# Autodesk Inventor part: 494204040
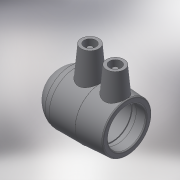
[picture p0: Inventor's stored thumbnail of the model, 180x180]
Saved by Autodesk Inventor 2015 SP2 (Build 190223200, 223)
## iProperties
Created: 2017-06
Part Number: 494204040
Material: Generic
Description: PLASSON END CAP MONOLITHIC 40
Document SubType Name: Modeling
Designer: Кирилл
Density: 1 g/cm^3
Appearance: Default
Author: Кирилл
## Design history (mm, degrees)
derived "494204.ipt"
feature "Solid1::494204.ipt"
tag "TaggingFeature1"
body "Solid1"
other parameters: "d1" = 1, "d2" = 48, "d4" = 55, "d5" = 7, "d7" = 1.65, "d8" = 24.5, "d10" = 1.1, "d11" = 14, "d12" = 168 deg, "d13" = 4.66667, "d15" = 51, "d16" = 15, "d17" = 35, "d18" = 1, "d20" = 5 deg, "d21" = 45.9, "d22" = 15, "d23" = 1, "d24" = 58.8, "d26" = 5 deg, "d27" = 4, "d29" = 14, "d30" = 0, "d31" = 4, "d33" = 14, "d34" = 0, "d37" = 36, "d38" = 48, "d39" = 55.2, "d40" = 44, "d41" = 2, "d42" = 0, "d44" = 360 deg, "d46" = 3, "d47" = 0, "d48" = 3, "d49" = 0, "L_1" = 48, "D_" = 55, "A_" = 51, "d_2" = 12
